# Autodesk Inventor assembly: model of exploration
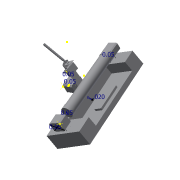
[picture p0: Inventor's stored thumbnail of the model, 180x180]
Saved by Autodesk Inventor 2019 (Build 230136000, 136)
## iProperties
Created: 2020-04
Part Number: model of exploration
Document SubType Name: Assembly
Designer: Krupashree
Author: Krupashree
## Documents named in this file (5)
- A:\sec sem notes\Engg explorRION\MODELLING\model of exploration.iam
- A:\sec sem notes\Engg explorRION\MODELLING\motor.ipt
- A:\sec sem notes\Engg explorRION\MODELLING\body final.ipt
- A:\sec sem notes\Engg explorRION\MODELLING\pen to holder.iam
- A:\sec sem notes\Engg explorRION\MODELLING\cylinder part new.iam
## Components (4 placed, 4 different names)
1. body final:1 — Mate:1, Mate:3
2. motor:1 — Mate:1, Mate:2
3. pen to holder:1 [sub-assembly] — Flush:1, Mate:2
4. cylinder part new:1 [sub-assembly] — Mate:3
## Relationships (4: Mate 3, Flush 1)
- Mate:1: body final:1 ↔ motor:1
- Flush:1: pen to holder:1
- Mate:2: motor:1 ↔ pen to holder:1
- Mate:3: body final:1 ↔ cylinder part new:1
